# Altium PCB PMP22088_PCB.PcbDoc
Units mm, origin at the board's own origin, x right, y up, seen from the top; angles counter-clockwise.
Board outline 25.4 x 38.1 mm, 2 copper layers (Top Layer, Bottom Layer), stack 1.575 mm thick; 47 components, 29 nets, 105 pads, 52 vias.
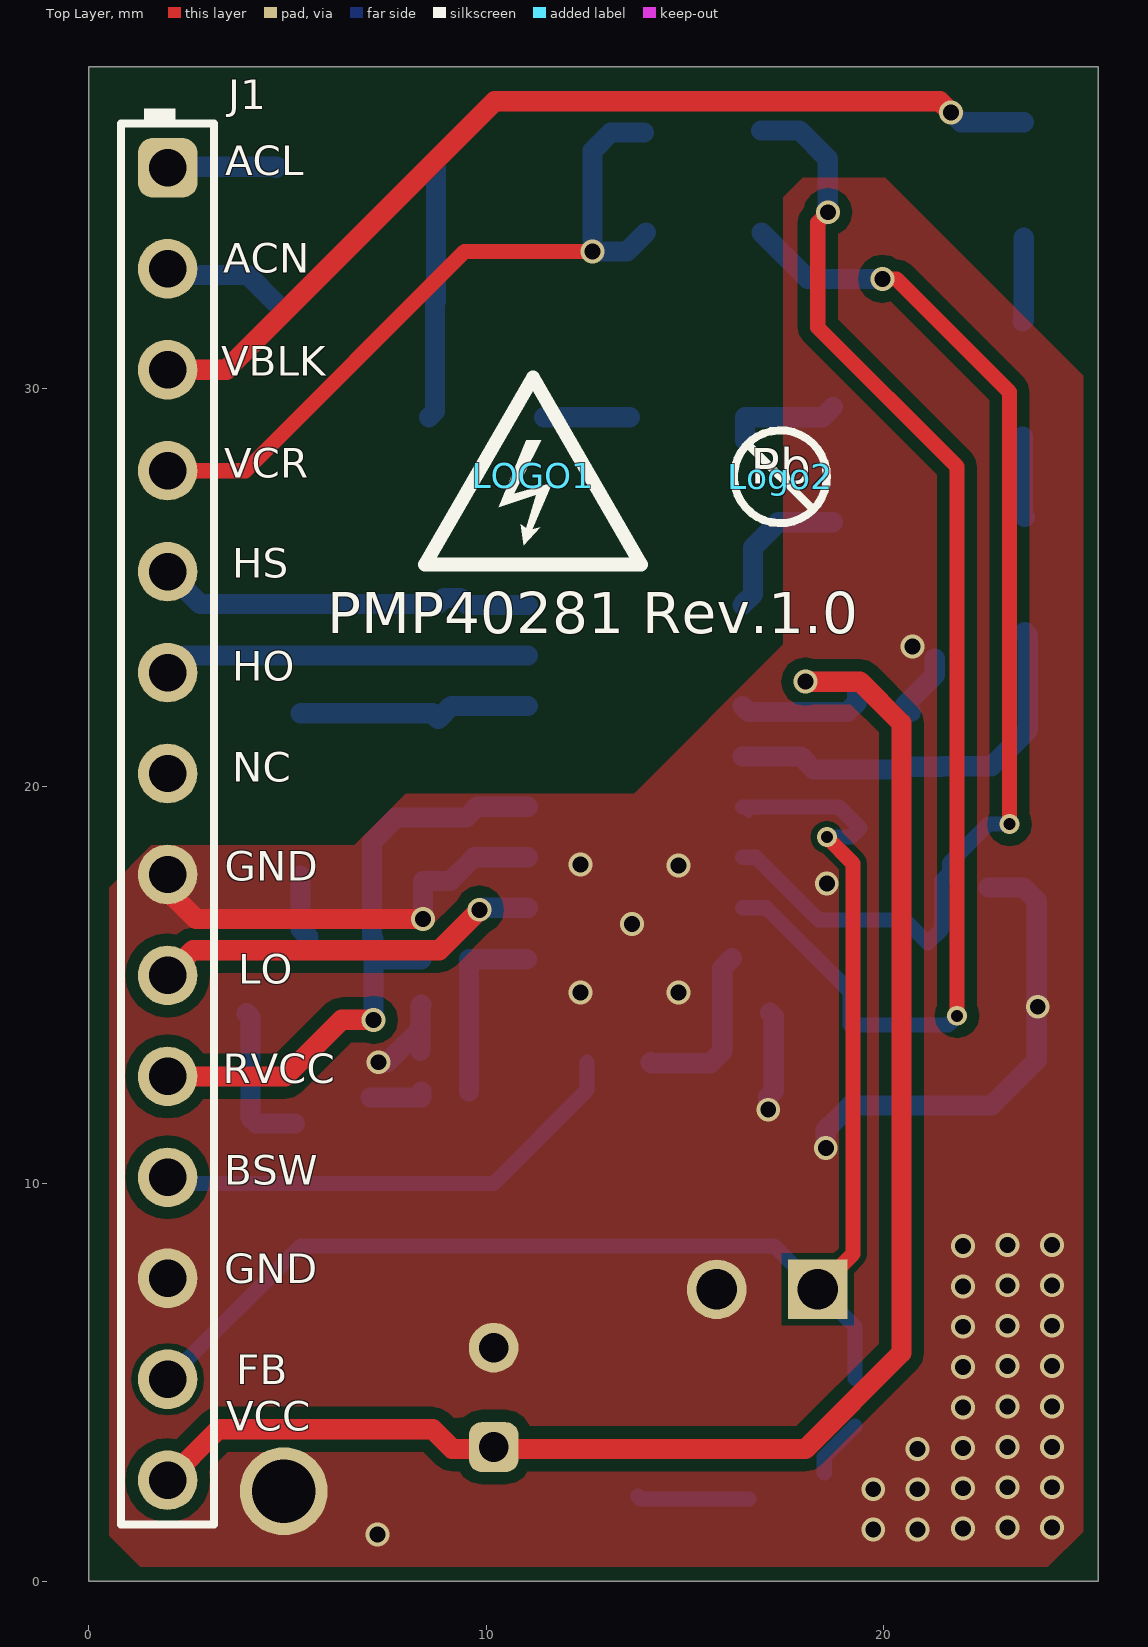
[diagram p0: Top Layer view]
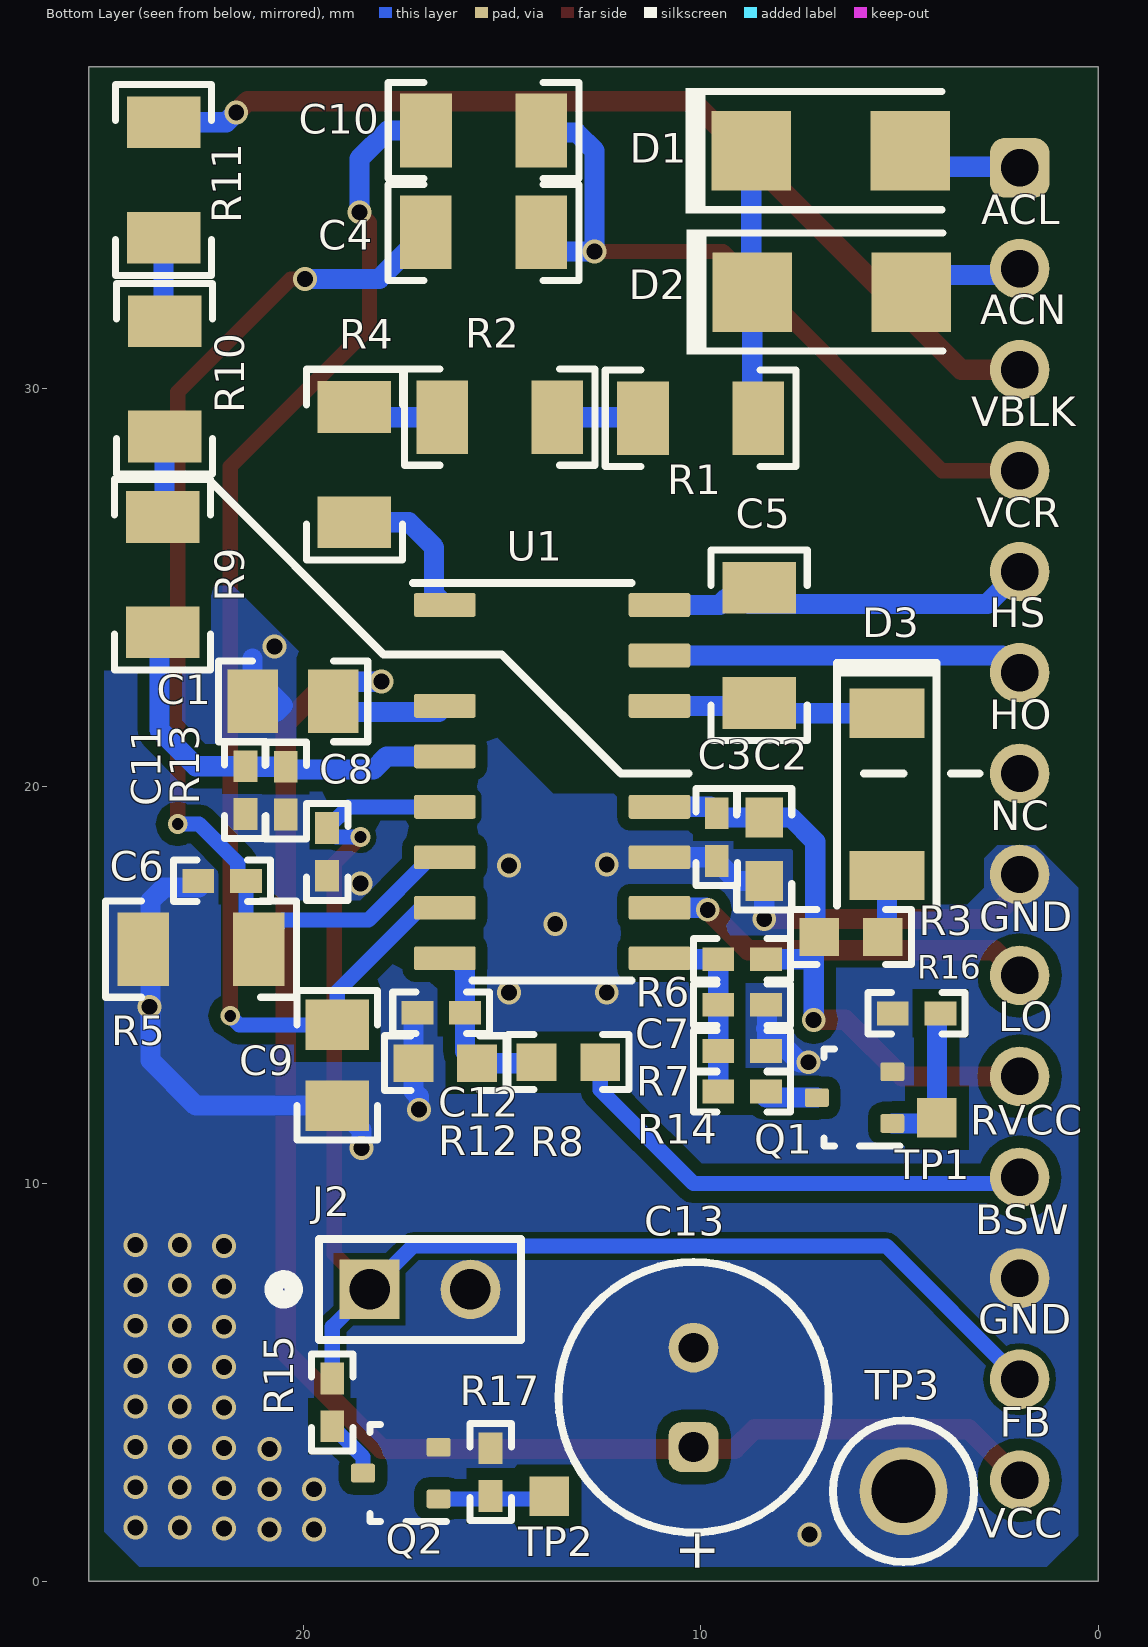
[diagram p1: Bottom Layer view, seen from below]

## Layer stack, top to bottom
Top Solder: solder mask 0.0102, Solder Resist, Dk 3.5
Top Layer: signal copper 0.0356
Dielectric1: core 1.5037, FR-4, Dk 4.8
Bottom Layer: signal copper 0.0356
Bottom Solder: solder mask 0.0102, Solder Resist, Dk 3.5

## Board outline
0,0 25.4,0 25.4,38.1 0,38.1

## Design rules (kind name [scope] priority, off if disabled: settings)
AcuteAngle [All] p1: minimum=4.50000000000000E+0001 checktracksonly=FALSE
AssemblyTestPointUsage [All] p1: valid=2
BoardOutlineClearance BoardOutlineClearance_MountingHoles [OnCopper and InComponentClass('Mounting Holes')] p1: gap=0.3
BoardOutlineClearance BoardOutlineClearance_Poly [OnCopper and IsPoly] p2: gap=0.3
BoardOutlineClearance [OnCopper and Not InComponentClass('Logo') and not InComponentClass('FiducialMark') and not InRegion(1000,500,4000,800) and not InPoly] p3: gap=0.3
Clearance Clearance_FB [InNet('FB') vs InNet('GND')] p1: gap=0.152
Clearance Clearance_Keepouts [((IsTrack Or IsArc) And Not InPoly) And IsFree and IsKeepOut vs ((IsTrack Or IsArc) And Not InPoly) And IsFree and IsKeepOut] p2: gap=0.2
Clearance Clearance_Poly [InPolygon] p3: gap=0.3
Clearance [All] p4: gap=0.2
ComponentClearance ComponentClearance_TPPAD [InComponent('TP1') vs InComponent('J1')] p1: gap=0.254 collisioncheckmode=3 verticalgap=0.254 showdistances=FALSE
ComponentClearance ComponentClearance_MountingHoles_FiducialMarks [InComponentClass('Mounting Holes') vs InComponentClass('FiducialMark')] p2: gap=1.27 collisioncheckmode=3 verticalgap=0.254 showdistances=FALSE
ComponentClearance ComponentClearance_Shunt [InComponentClass('Header') vs InComponentClass('Shunt')] p3: gap=0 collisioncheckmode=3 verticalgap=0 showdistances=FALSE
ComponentClearance ComponentClearance_Logo [InComponentClass('Logo')] p4: gap=1.27 collisioncheckmode=3 verticalgap=0.254 showdistances=FALSE
ComponentClearance ComponentClearance_ScrewToNut [(HasFootprint('NY PMS 440 0025 PH')) vs (HasFootprint('Keystone_1902C'))] p5: gap=0.127 collisioncheckmode=3 verticalgap=0.254 showdistances=FALSE
ComponentClearance ComponentClearance_MountingHoles [InComponentClass('Mounting Holes')] p6: gap=6.35 collisioncheckmode=3 verticalgap=2540 showdistances=FALSE
ComponentClearance ComponentClearance_SmallPassives [HasFootprint('0201*') or HasFootprint('0402*') or HasFootprint('0508') or HasFootprint('0603*') or HasFootprint('0612') or HasFootprint('0805*') or HasFootprint('0815*') or HasFootprint('0830*') or HasFootprint('1206*') or HasFootprint('1210*') or HasFootprint('1808*') or HasFootprint('1812*') or HasFootprint('1825*') or HasFootprint('2010*') or HasFootprint('2220*') or HasFootprint('2225*') or HasFootprint('2512*') or HasFootprint('2728*') or HasFootprint('3518*') vs HasFootprint('0201*') or HasFootprint('0402*') or HasFootprint('0508') or HasFootprint('0603*') or HasFootprint('0612') or HasFootprint('0805*') or HasFootprint('0815*') or HasFootprint('0830*') or HasFootprint('1206*') or HasFootprint('1210*') or HasFootprint('1808*') or HasFootprint('1812*') or HasFootprint('1825*') or HasFootprint('2010*') or HasFootprint('2220*') or HasFootprint('2225*') or HasFootprint('2512*') or HasFootprint('2728*') or HasFootprint('3518*')] p7: gap=0.38 collisioncheckmode=3 verticalgap=0.254 showdistances=FALSE
ComponentClearance ComponentClearance_THtoSMT [IsThruComponent vs IsSMTComponent] p8: gap=1.016 collisioncheckmode=3 verticalgap=0.762 showdistances=FALSE
ComponentClearance ComponentClearance_THtoTH [IsThruComponent vs IsThruComponent] p9: gap=0.762 collisioncheckmode=3 verticalgap=0.762 showdistances=FALSE
ComponentClearance [All] p10: gap=0.762 collisioncheckmode=3 verticalgap=0.254 showdistances=FALSE
DiffPairsRouting [All] p1: maxlimit=2.54 minlimit=0.254 mostfreqgap=0.254 toplayer_minwidth=0.381 toplayer_maxwidth=0.381 toplayer_prefwidth=0.381 bottomlayer_minwidth=0.381 bottomlayer_maxwidth=0.381 bottomlayer_prefwidth=0.381 maxuncoupledlength=25.4
FabricationTestPointUsage TestPointUsage [All] p1: valid=2 allowmultiple=FALSE
FabricationTestpoint Testpoint [All] p1: side=3 testpointundercomponent=TRUE minsize=1.016 maxsize=2.54 preferedsize=1.524 minholesize=0 maxholesize=1.016 preferedholesize=0.813 testpointgrid=0.025 allowsidetop=TRUE allowsidebottom=TRUE usegrid=TRUE gridtolerance=0
FanoutControl Fanout_LCC [IsLCC] p1: bgadir=Out bgaviamode=Centered fanoutstyle=Auto fanoutdirection=Alternating viagrid=0.025 // Fanout_LCC (Default Rule)
FanoutControl Fanout_BGA [IsBGA] p2: bgadir=Out bgaviamode=Centered fanoutstyle=Auto fanoutdirection=Alternating viagrid=0.025 // Fanout_BGA (Default Rule)
FanoutControl Fanout_Default [All] p4: bgadir=Out bgaviamode=Centered fanoutstyle=Auto fanoutdirection=Alternating viagrid=0.025 // Fanout_Default (Default Rule)
FanoutControl Fanout_Small [(CompPinCount < 5)] p5: bgadir=Out bgaviamode=Centered fanoutstyle=Auto fanoutdirection=OutThenIn viagrid=0.025 // Fanout_Small (Default Rule)
HoleSize [All] p1: absolutevalues=TRUE maxlimit=6.375 minlimit=0.2 maxpercent=80.000 minpercent=20.000
HoleToHoleClearance [All] p1: gap=0.2 allowstackedmicrovias=TRUE
MinimumAnnularRing MinimumAnnularRing_ThermalPadVias [IsVia and InAnyComponent] p1: minimumring=0.1
MinimumAnnularRing [All] p2: minimumring=0.1
MinimumSolderMaskSliver MinimumSolderMaskSliver_Logo [InComponentClass('Logo') vs InComponentClass('Logo')] p1: minsoldermaskwidth=0
MinimumSolderMaskSliver [All] p2: minsoldermaskwidth=0
PlaneConnect [All] p1: planeconnectstyle=Direct reliefexpansion=0.254 reliefentries=4 reliefconductorwidth=0.254 reliefairgap=0.254
PolygonConnect [All] p1: connectstyle=Direct reliefconductorwidth=0.254 reliefentries=4 polygonreliefangle="90 Angle" airgapwidth=0.254
RoutingVias ThermalPadVias [IsVia and InAnyComponent] p1: holewidth=0.2 width=0.5 viastyle="Through Hole" minholewidth=0.2 minwidth=0.2 maxholewidth=0.33 maxwidth=0.6
RoutingVias [All] p2: holewidth=0.406 width=0.864 viastyle="Through Hole" minholewidth=0.2 minwidth=0.4 maxholewidth=1.016 maxwidth=1.651
SilkToBoardRegionClearance [Not ((IsComment or IsDesignator) And (Hide <> 'False')) and not InRegion(1000,500,4000,800)] p1:
SilkToSilkClearance SilkToSilkClearance_Pb-FreeLogo [(HasFootprint('Pb-Free_Overlay_Medium') OR HasFootprint('Pb-Free_Overlay_Small')) vs (HasFootprint('Pb-Free_Overlay_Medium') OR HasFootprint('Pb-Free_Overlay_Small'))] p1: silktosilkclearance=0
SilkToSilkClearance [All] p2: silktosilkclearance=0
SilkToSolderMaskClearance SilkToComponentPadClearance [(IsPad or IsFill or IsRegion) and InAnycomponent] p1: minsilkscreentomaskgap=0 clearancetoexposedcopper=TRUE
SilkToSolderMaskClearance "Silk to Solder Mask Opening" [All] p2: minsilkscreentomaskgap=0 clearancetoexposedcopper=FALSE
SolderMaskExpansion [All] p1: expansion=0.05
Width [All] p1: maxlimit=2.54 minlimit=0.381 preferedwidth=0.381 checkconnectedcopper=TRUE
14 further rules are at their usual default settings.

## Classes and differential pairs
component class Header: J1 J2
component class AssemblyNote: ZZ1 ZZ2 ZZ3 ZZ4

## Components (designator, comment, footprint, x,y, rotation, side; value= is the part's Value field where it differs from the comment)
C1 "C2012X7R1V225K085AC" 0805_HV 20.263,22.136 r180 bottom
C2 "GRM188Z71C475KE21D" 0603#1 6.298,13.233 r90 bottom
C3 "GRM155R71C104KA88D" 0402 9.601,18.72 r90 bottom
C4 "GRM31A5C2J151JW01D" 1206 15.471,33.934 r0 bottom
C5 "C1206C225K4RACTU" 1206 8.534,23.546 r90 bottom
C6 "GRM1555C1H3R3CA01D" 0402 22.049,17.619 r0 bottom
C7 "GRM155R71C154KA12D" 0402 8.966,14.503 r180 bottom
C8 "GRM1555C1H470FA01D" 0402 19.406,18.348 r270 bottom
C9 "GRM2195C1H153JA01D" 0805_HV 19.152,12.979 r90 bottom
C10 "GRM31A5C2J151JW01D" 1206 15.469,36.5 r0 bottom
C11 "GRM1555C1H221JA01D" 0402 21.463,19.901 r270 bottom
C12 "GRM1555C1H3R9CA01D" 0402 16.535,14.3 r0 bottom
C13 "35ZLQ120MEFC6.3X11" ZLQ_630x1100 10.185,4.623 r90 bottom
D1 "MURA160T3G" SMA 6.732,35.992 r180 bottom
D2 "MURA160T3G" SMA 6.707,32.436 r180 bottom
D3 "ES1JAF" SMAF 5.321,19.796 r270 bottom
J1 "4-644694-4" TE_4-644694-4 -0.051,19.05 r270 top locked
J2 "5-146261-1" CONN_5-146261-1 17.069,7.341 r180 bottom
LOGO1 "DANGER HIGH VOLTAGE" IEC_HighVoltage_Small 11.176,27.813 r0 top
Logo2 "Pb-Free Symbol" Pb-Free_Overlay_Small 17.399,27.788 r0 top
Q1 "2N7002KW" SOT-323 6.133,12.164 r0 bottom
Q2 "2N7002KW" SOT-323 17.551,2.718 r0 bottom
R1 "CRCW12061K65FKEA" 1206 10.008,29.261 r0 bottom
R2 "CRCW12061K65FKEA" 1206 15.062,29.286 r0 bottom
R3 "CRCW06032R20JNEA" 0603#2 6.223,16.205 r0 bottom
R4 "CRCW12061K65FKEA" 1206 18.72,28.092 r90 bottom
R5 "CRCW1206174RFKEA" 1206 22.578,15.9 r180 bottom
R6 "CRCW0402750KFKED" 0402 8.966,15.646 r180 bottom
R7 "CRCW0402487KFKED" 0402 8.966,13.335 r0 bottom
R8 "CRCW060335K7FKEA" 0603#2 13.335,13.056 r180 bottom
R9 "CRCW12064M99FKEA" 1206 23.546,25.324 r90 bottom
R10 "CRCW12064M99FKEA" 1206 23.495,30.251 r90 bottom
R11 "CRCW12064M99FKEA" 1206 23.52,35.255 r90 bottom
R12 "CRCW060310K0FKEA" 0603#2 16.434,13.03 r180 bottom
R13 "CRCW0402140KFKED" 0402 20.447,19.888 r90 bottom
R14 "CRCW0402487KFKED" 0402 8.966,12.319 r0 bottom
R15 "CRCW0402487KFKED" 0402 19.279,4.496 r90 bottom
R16 "CRCW040210K0FKED" 0402 4.574,14.286 r180 bottom
R17 "CRCW040210K0FKED" 0402 15.291,2.743 r270 bottom
TP1 "TESTPOINT" PAD_1MM_SQUARE 4.064,11.659 r0 top
TP2 "TESTPOINT" PAD_1MM_SQUARE 13.818,2.134 r90 top
TP3 "5011" Keystone5011 4.902,2.261 r90 bottom
U1 "UCC25630-1DDBR" DDB0014A 13.743,20.117 r180 bottom
ZZ1 "This Assembly Note is for PCB labels only" AssemblyNoteLabel 4.699,100.025 r0 top
ZZ2 "These assemblies are ESD sensitive, ESD precautions shall be observed." AssemblyNote 4.699,97.259 r0 top
ZZ3 "These assemblies must be clean and free from flux and all contaminants. Use of no clean flux is not acceptable." AssemblyNote 4.699,95.01 r0 top
ZZ4 "These assemblies must comply with workmanship standards IPC-A-610 Class 2, unless otherwise specified." AssemblyNote 4.699,92.761 r0 top

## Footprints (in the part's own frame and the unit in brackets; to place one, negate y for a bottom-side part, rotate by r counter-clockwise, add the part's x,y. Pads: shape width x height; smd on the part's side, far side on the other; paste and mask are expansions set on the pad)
0402 [mm] "0402 from SM-752 data"
  rect 0.8x0.6 smd: 1(-0.6,0) 2(0.6,0)
  silkscreen extent -1.22,-0.52 1.22,0.52, body extent -0.55,-0.3 0.55,0.3, height 0.6
0603#1 [mm] "0603 from SM-752 data"
  rect 1x0.95 smd: 1(4.382,2.108) 2(5.982,2.108)
  silkscreen extent 3.66,1.42 6.71,2.8, body extent 4.31,1.63 6.06,2.58, height 1
0603#2 [mm] "0603 from SM-752 data"
  rect 1x0.95 smd: 1(-0.8,0) 2(0.8,0)
  silkscreen extent -1.52,-0.69 1.52,0.69, body extent -0.87,-0.47 0.87,0.47, height 1
0805_HV [mil] "0805 with 30mil clearance between pads"
  rect 50x63 smd: 1(-40,0) 2(40,0)
  silkscreen extent -74,-40 74,40, body extent -43,-29 43,29, height 57
1206 [mm] "1206 from SM-752 data"
  rect 1.3x1.85 smd: 1(-1.45,0) 2(1.45,0)
  silkscreen extent -2.4,-1.21 2.4,1.21, body extent -1.7,-0.9 1.7,0.9, height 1.35
AssemblyNote [mm] "Assembly Note"
AssemblyNoteLabel [mm] "Assembly Note for PCB Labels"
CONN_5-146261-1 [mm] "Sullins"
  rect 1.5x1.5 hole 1.02: 1(-1.27,0)
  round 1.5 hole 1.02: 2(1.27,0)
  silkscreen extent -3.68,-1.27 2.54,1.27, body extent -2.51,-1.27 2.51,1.27, height 10.87
DDB0014A [mm] "SMD, 14-Leads, Body 3.9x9.9mm, Pitch 1.27mm"
  rrect17% 1.55x0.6 smd: 1(-2.7,4.445) 3(-2.7,1.905) 4(-2.7,0.635) 5(-2.7,-0.635) 6(-2.7,-1.905) 7(-2.7,-3.175) 8(-2.7,-4.445) 9(2.7,-4.445) 10(2.7,-3.175) 11(2.7,-1.905) 12(2.7,-0.635) 14(2.7,1.905) 15(2.7,3.175) 16(2.7,4.445)
  silkscreen extent -3.5,-5 2,5, body extent -3.01,-4.95 3.01,4.95, height 1.75
IEC_HighVoltage_Small [mm]
  silkscreen extent -2.72,-2.24 2.72,2.47
Keystone5011 [mil] "Keystone Multipurpose loops"
  round 87 hole 63: 1(0,0)
  silkscreen extent -70,-70 70,70, body extent -63,-63 63,62, height 319
PAD_1MM_SQUARE [mm]
  rect 1x1 smd far side: 1(0,0)
Pb-Free_Overlay_Small [mm]
  silkscreen extent -1.16,-1.17 1.17,1.17
SMA [mm] "Molded Diode, 2-Leads, Body 4.3x2.6mm, IPC Medium Density, based on OnSemi component dimensions and land pattern"
  rect 2x2 smd: 1(-2,0) 2(2,0)
  silkscreen extent -3.66,-1.57 2.79,1.57, body extent -2.6,-1.3 2.6,1.3, height 2.42
SMAF [mm] "SMD, 2-Leads, Body 3.8x2.5mm"
  rect 1.24x1.89 smd: 1(-2.04,0) 2(2.04,0)
  silkscreen extent -3.4,-1.3 2.8,1.3, body extent -2.35,-1.25 2.35,1.25, height 1
SOT-323 [mm] "Diodes Inc recommended land pattern.  2016-02-24"
  rrect21% 0.6x0.47 smd: 1(-0.95,0.65) 2(-0.95,-0.65) 3(0.95,0)
  silkscreen extent -1.14,-1.22 0.77,1.22, body extent -1.13,-1.13 1.12,1.12, height 1.13
TE_4-644694-4 [mm] "Header, 100 mil, 14x1, R/A, TH"
  rrect50% 1.5x1.5 hole 0.94: 1(-16.51,2.032)
  round 1.5 hole 0.94: 2(-13.97,2.032) 3(-11.43,2.032) 4(-8.89,2.032) 5(-6.35,2.032) 6(-3.81,2.032) 7(-1.27,2.032) 8(1.27,2.032) 9(3.81,2.032) 10(6.35,2.032) 11(8.89,2.032) 12(11.43,2.032) 13(13.97,2.032) 14(16.51,2.032)
  silkscreen extent -18,0.86 17.63,3.2, body extent -17.63,-5.74 17.63,3.2, height 6.67
ZLQ_630x1100 [mm] "TH, 2-Leads, Dia 6.3mm, Pin Spacing 2.5mm"
  rrect50% 1.25x1.25 hole 0.75: 1(-1.25,0)
  round 1.25 hole 0.75: 2(1.25,0)
  silkscreen extent -3.4,-3.4 3.41,3.4, body extent -3.4,-3.4 3.41,3.4, height 12.51

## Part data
C1: "CAP, CERM, 2.2 μF, 35 V, +/- 10%, X7R, 0805"
C2: "CAP, CERM, 4.7 μF, 16 V, +/- 10%, X7R, 0603"
C3: "CAP, CERM, 0.1 μF, 16 V, +/- 10%, X7R, 0402"
C4 C10: "CAP, CERM, 150 pF, 630 V, +/- 5%, C0G/NP0, 1206"
C5: "CAP, CERM, 2.2 μF, 16 V, +/- 10%, X7R, 1206"
C6: "CAP, CERM, 3.3 pF, 50 V, +/- 5%, C0G/NP0, 0402"
C7: "CAP, CERM, 0.15 μF, 16 V, +/- 10%, X7R, 0402"
C8: "CAP, CERM, 47 pF, 50 V, +/- 1%, C0G/NP0, 0402"
C9: "CAP, CERM, 0.015 μF, 50 V, +/- 5%, C0G/NP0, 0805"
C11: "CAP, CERM, 220 pF, 50 V, +/- 5%, C0G/NP0, 0402"
C12: "CAP, CERM, 3.9 pF, 50 V, +/- 5%, C0G/NP0, 0402"
C13: "CAP, AL, 120 μF, 35 V, +/- 20%, TH"
D1 D2: "Diode, Ultrafast, 600 V, 1 A, AEC-Q101, SMA"
D3: "Diode, Ultrafast, 600 V, 1 A, AEC-Q101, SMAF"
J1: "Header, 100 mil, 14x1, Tin, R/A, TH"
J2: "Header, 100mil, 2x1, Gold, TH"
LOGO1: library part IEC_HighVoltage, "IEC 61010-1 High Voltage Warning"
Logo2: library part Pb-Free
Q1 Q2: "MOSFET, N-CH, 60 V, 0.31 A, SOT-323"
R1 R2 R4: "RES, 1.65 k, 1%, 0.25 W, 1206"
R3: "RES, 2.2, 5%, 0.1 W, 0603"
R5: "RES, 174, 1%, 0.25 W, 1206"
R6: "RES, 750 k, 1%, 0.063 W, 0402"
R7 R14 R15: "RES, 487 k, 1%, 0.063 W, 0402"
R8: "RES, 35.7 k, 1%, 0.1 W, 0603"
R9 R10 R11: "RES, 4.99 M, 1%, 0.25 W, 1206"
R12: "RES, 10.0 k, 1%, 0.1 W, 0603"
R13: "RES, 140 k, 1%, 0.063 W, 0402"
R16 R17: "RES, 10.0 k, 1%, 0.063 W, 0402"
TP1 TP2: library part PAD_1MM_SQUARE, "1.0x1.0mm pad, square, SMD"
TP3: "Test Point, Multipurpose, Black, TH"
U1: "Enhanced LLC Resonant Controller with Driver, DDB0014A (SOIC-14)"
ZZ1: library part AssemblyNoteLabel
ZZ2 ZZ3 ZZ4: library part AssemblyNote

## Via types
v1: diameter 0.6, hole 0.4, Top Layer to Bottom Layer, 49 vias
v2: diameter 0.5, hole 0.3, Top Layer to Bottom Layer, 3 vias

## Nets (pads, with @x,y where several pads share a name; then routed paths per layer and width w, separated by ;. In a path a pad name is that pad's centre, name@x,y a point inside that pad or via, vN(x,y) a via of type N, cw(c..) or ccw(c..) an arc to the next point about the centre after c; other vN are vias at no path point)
ACL: D1.2 J1.1 | length 2.8
  Bottom Layer w0.508: J1.1 2.007,35.585 4.732,35.585 D1.2@4.707,35.56
ACN: D2.2 J1.2 | length 3.1
  Bottom Layer w0.508: J1.2 2.134,32.868 3.996,32.868 D2.2@4.707,32.156
BLK: C11.1 R9.1 R13.2 U1.4 | length 10.2
  Bottom Layer w0.508: U1.4 17.907,20.752 18.237,20.422 20.38,20.422 R13.2 21.45,20.488 C11.1 22.711,20.501 23.622,21.412 23.622,23.798 R9.1
BSW: J1.11 R8.2 | length 12.3
  Bottom Layer w0.381: J1.11 2.134,10.008 10.185,10.008 12.535,12.357 R8.2
FB: C8.1 J1.13 J2.1 R15.2 U1.5 | length 37.5
  Top Layer w0.254: J2.1@18.324,7.036 18.288,7.072 J2.1@18.448,7.232
  Top Layer w0.381: J2.1 19.228,8.23 19.228,18.059 v2(18.567,18.72)
  Bottom Layer w0.254: U1.5 U1.5@16.595,19.329
  Bottom Layer w0.381: J1.13 5.335,8.434 17.246,8.434 J2.1 19.279,6.401 R15.2 ; U1.5 18.872,19.482 C8.1 19.177,18.72 v2(18.567,18.72)
GND: C1.1 C2.1 C3.1 C6.2 C7.2 C8.2 C9.1 C11.2 C12.2 C13.2 J1.8 J1.12 J2.2 Q1.2 Q2.2 R5.1 R7.1 R12.1 R13.1 R16.1 R17.1 TP3.1 U1.11 | length 29.7
  Top Layer w0.508: J1.8 1.981,17.374 2.692,16.662 v1(8.407,16.662)
  Bottom Layer w0.508: v1(7.29,13.056) 7.509,13.056 7.585,13.132 8.357,13.903 8.341,13.919 ; 8.315,13.945 8.341,13.919 ; R7.1@8.341,13.335 8.341,13.919 ; C7.2 8.341,14.478 8.341,13.919 ; v1(8.407,16.662) 8.406,16.664 C2.1 9.096,17.615 C3.1 9.693,18.212 U1.11 ; v1(17.094,11.862) 17.094,12.192 17.234,12.332 R12.1 17.234,14.202 C12.2 ; v1(18.542,10.897) 18.542,11.354 18.644,11.455 18.749,11.561 C9.1 22.708,11.963 23.851,13.106 23.851,15.9 23.851,17.12 23.52,17.45 C6.2@22.635,17.45 ; C1.1@20.688,21.869 20.523,22.034 21.285,22.796 21.285,23.216
  other v1: 7.264,1.168 19.736,1.295 20.853,1.295 21.996,1.321 23.114,1.346 24.232,1.346 19.736,2.311 20.853,2.311 21.996,2.337 23.114,2.362 24.232,2.362 20.853,3.327 21.996,3.353 23.114,3.378 24.232,3.378 21.996,4.369 23.114,4.394 24.232,4.394 21.996,5.385 23.114,5.41 24.232,5.41 21.996,6.401 23.114,6.426 24.232,6.426 21.996,7.417 23.114,7.442 24.232,7.442 21.996,8.433 23.114,8.458 24.232,8.458 23.876,14.453 12.37,14.808 14.834,14.808 13.665,16.535 18.567,17.551 14.834,18.009 12.37,18.034 20.726,23.52
HB: C5.1 D3.1 U1.14 | length 5.9
  Bottom Layer w0.508: D3.1 8.642,21.836 8.788,21.689 9.121,22.022 U1.14
HO: J1.6 U1.15 | length 9.2
  Bottom Layer w0.508: J1.6 2.413,23.292 U1.15
HS: C5.2 J1.5 U1.16 | length 9.5
  Bottom Layer w0.508: J1.5 2.792,24.589 8.788,24.589 8.939,24.74 9.347,24.74 9.525,24.562 U1.16
LL: C7.1 R6.1 R7.2 R14.2 U1.9 | length 4.8
  Bottom Layer w0.254: U1.9@11.017,15.646 U1.9
  Bottom Layer w0.508: R14.2 C7.1 R6.1 U1.9@11.017,15.646
LO: J1.9 U1.10 | length 9.8
  Top Layer w0.508: J1.9 2.616,15.875 8.814,15.875 v1(9.83,16.891)
  Bottom Layer w0.508: v1(9.83,16.891) 9.881,16.942 U1.10
NetC4_2: C4.2 C6.1 R5.2 U1.6 | length 28.5
  Top Layer w0.381: v1(19.964,32.766) 20.32,32.766 23.165,29.921 v2(23.165,19.05)
  Bottom Layer w0.381: U1.6 16.789,18.212 18.364,16.637 20.523,16.637 21.105,16.055 21.449,16.399 C6.1 21.653,17.824 21.653,18.072 22.631,19.05 v2(23.165,19.05)
  Bottom Layer w0.508: C4.2 18.089,32.766 v1(19.964,32.766)
NetC9_2: C9.2 C10.2 U1.7 | length 32.3
  Top Layer w0.381: v1(18.593,34.442) 18.339,34.188 18.339,31.547 21.844,28.042 v2(21.844,14.224)
  Bottom Layer w0.381: U1.7 17.043,16.942 19.152,14.834 C9.2 21.615,13.995 v2(21.844,14.224)
  Bottom Layer w0.508: C10.2 17.882,36.5 18.593,35.789 v1(18.593,34.442)
NetC12_1: C12.1 R8.1 R12.2 U1.8 | length 4.4
  Bottom Layer w0.508: R8.1 14.16,13.03 R12.2 15.935,13.332 C12.1 15.935,15.427 U1.8@16.18,15.672
NetD1_1: D1.1 D2.1 R1.1 | length 6.4
  Bottom Layer w0.508: R1.1@8.558,29.286 8.707,29.435 8.707,32.156 8.732,32.182 D1.1@8.732,35.585
NetD3_2: D3.2 R3.1 | length 1.6
  Bottom Layer w0.508: D3.2 5.321,16.409 R3.1@5.525,16.205
NetQ1_1: Q1.1 R16.2 TP1.1 | length 3.8
  Bottom Layer w0.508: R16.2 4.064,14.195 TP1.1 4.208,11.514 Q1.1
NetQ1_3: Q1.3 R14.1 | length 1.4
  Bottom Layer w0.508: Q1.3 8.366,12.164 R14.1
NetQ2_1: Q2.1 R17.2 TP2.1 | length 2.8
  Bottom Layer w0.381: TP2.1 13.883,2.068 Q2.1
NetQ2_3: Q2.3 R15.1 | length 1.5
  Bottom Layer w0.381: Q2.3 18.501,3.119 R15.1
NetR1_2: R1.2 R2.1 | length 2.2
  Bottom Layer w0.508: R1.2@11.458,29.286 R2.1
NetR2_2: R2.2 R4.2 | length 2.9
  Bottom Layer w0.508: R2.2@16.512,28.704 R2.2 18.464,29.286 R4.2
NetR4_1: R4.1 U1.1 | length 3.8
  Bottom Layer w0.508: U1.1 16.713,24.832 16.713,26.01 17.346,26.642 R4.1
NetR9_2: R9.2 R10.1 | length 2
  Bottom Layer w0.508: R10.1 23.495,26.825 R9.2
NetR10_2: R10.2 R11.1 | length 2.1
  Bottom Layer w0.508: R10.2 23.52,31.727 R11.1
RVCC: C2.2 C3.2 J1.10 R3.2 R6.2 U1.12 | length 16.1
  Top Layer w0.508: J1.10 4.942,12.7 6.364,14.122 v1(7.163,14.122)
  Bottom Layer w0.508: v1(7.163,14.122) R3.2@7.163,16.167 ; R6.2 7.391,15.646 7.163,15.875 R3.2@7.163,16.167 ; U1.12 9.763,19.482 C3.2 9.496,19.215 C2.2 7.734,19.215 7.125,18.605 7.125,16.205 R3.2@7.163,16.167
VBLK: J1.3 R11.2 | length 24.6
  Top Layer w0.508: J1.3 3.454,30.48 10.211,37.236 21.412,37.236 v1(21.692,36.957)
  Bottom Layer w0.508: v1(21.692,36.957) 21.943,36.705 R11.2
VCC: C1.2 C13.1 J1.14 U1.3 | length 43.7
  Top Layer w0.508: J1.14 3.261,3.819 8.652,3.819 9.144,3.327 18.034,3.327 20.447,5.74 20.447,21.59 19.406,22.631 v1(18.034,22.631)
  Bottom Layer w0.508: U1.3 16.595,21.869 19.088,21.869 19.329,22.111 19.329,22.53 19.228,22.631 v1(18.034,22.631)
VCR: C4.1 C10.1 J1.4 | length 18.6
  Top Layer w0.381: J1.4 3.937,27.94 9.449,33.452 v1(12.675,33.452)
  Bottom Layer w0.254: C10.1@13.968,36.449 C10.1
  Bottom Layer w0.508: C10.1@13.968,36.449 13.132,36.449 12.675,35.992 v1(12.675,33.452) 13.538,33.452 C4.1
pads on no net: J1.7

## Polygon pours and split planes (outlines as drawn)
GND on Top Layer "TOP_LAYER_GND_P000" (solid, remove dead copper, pour order 0): 6.68,18.517 7.976,19.812 13.716,19.812 17.475,23.571 17.475,34.823 17.958,35.306 20.041,35.306 25.019,30.328 25.019,1.499 25.019,1.245 24.13,0.356 1.295,0.356 0.508,1.143 0.508,17.45 1.575,18.517
GND on Bottom Layer "BOTTOM_LAYER_GND_P002" (solid, remove dead copper, pour order 2): 5.182,17.018 6.579,17.018 6.833,17.272 6.833,18.669 7.976,19.812 13.716,19.812 16.205,22.301 19.025,22.301 21.768,25.044 24.206,25.044 25.019,24.232 25.019,1.499 25.019,1.245 24.13,0.356 1.295,0.356 0.508,1.143 0.508,16.459 0.508,17.45 1.575,18.517 2.54,18.517 2.87,18.186 2.87,17.45 3.302,17.018

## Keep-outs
Keep-Out Layer:
  text ".Layer_Name" at 14.656,-21.806 h1.52

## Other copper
Top Layer:
  text ".Layer_Name" at 14.656,-21.806 h1.52
Bottom Layer:
  text ".Layer_Name" at 14.656,-21.806 h1.52

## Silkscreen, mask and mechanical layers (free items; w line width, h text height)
Top Overlay:
  text "ACL" at 3.429,35.128 h1.27
  text "ACN" at 3.378,32.664 h1.27
  text "VBLK" at 3.327,30.074 h1.27
  text "VCR" at 3.404,27.508 h1.27
  text "HS" at 3.607,24.994 h1.27
  text "PMP40281 Rev.1.0" at 5.994,23.515 h1.78
  text "HO" at 3.607,22.403 h1.27
  text "NC" at 3.607,19.863 h1.27
  text "GND" at 3.424,17.374 h1.27
  text "LO" at 3.759,14.775 h1.27
  text "RVCC" at 3.373,12.275 h1.27
  text "BSW" at 3.404,9.72 h1.27
  text "GND" at 3.404,7.239 h1.27
  text "FB" at 3.703,4.706 h1.27
  text "VCC" at 3.454,3.531 h1.27
  text ".Layer_Name" at 14.656,-21.806 h1.52
Bottom Overlay:
  lines w0.203: 2.997,20.32 3.708,20.32 ; 4.902,20.32 5.893,20.32 ; 10.312,20.32 12.014,20.32 15.011,23.317 17.196,23.317 17.983,23.317 22.479,27.813
  text "ACL" at 2.946,33.884 h1.27
  text "ACN" at 2.972,31.369 h1.27
  text "VBLK" at 3.2,28.804 h1.27
  text "VCR" at 3.073,26.264 h1.27
  text "HS" at 2.743,23.749 h1.27
  text "HO" at 2.743,21.184 h1.27
  text "NC" at 2.718,18.644 h1.27
  text "GND" at 2.992,16.104 h1.27
  text "LO" at 2.515,13.581 h1.27
  text "RVCC" at 3.221,10.98 h1.27
  text "BSW" at 3.099,8.476 h1.27
  text "GND" at 3.023,5.969 h1.27
  text "FB" at 2.484,3.385 h1.27
  text "VCC" at 3.023,0.838 h1.27
  text ".Layer_Name" at 14.656,-21.806 h1.52
Top Paste:
  text ".Layer_Name" at 14.656,-21.806 h1.52
Bottom Paste:
  text ".Layer_Name" at 14.656,-21.806 h1.52
Top Solder:
  rectangle: 10.922,10.998 17.501,19.126
  region: 21.438,9.144 21.438,5.258 18.212,2.032 6.909,2.032 6.909,0.457 18.212,0.457 23.927,0.457 24.74,1.27 24.74,9.144
  text ".Layer_Name" at 14.656,-21.806 h1.52
  text ".Layer_Name" at 14.656,-21.806 h1.52
Bottom Solder:
  rectangle: 6.807,0.406 8.179,1.676
  region: 21.438,9.144 21.438,4.216 18.212,0.991 18.212,0.457 23.927,0.457 24.74,1.27 24.74,9.144
  text ".Layer_Name" at 14.656,-21.806 h1.52
Drill Guide:
  text ".Layer_Name" at 14.656,-21.806 h1.52
M1 Board Outline:
  the board outline again, w0.203
  text ".Layer_Name" at 14.656,-21.806 h1.52
M2 Board Dimensions:
  rectangle: 0,-6.985 3.175,-3.81
  rectangle: 3.175,-10.16 12.7,-6.985
  lines w0.178: 0,-6.985 25.4,-6.985 ; 3.175,-10.16 3.175,-3.81 ; 6.35,-10.16 6.35,-3.81 ; 12.7,-10.16 12.7,-3.81 ; 19.05,-10.16 19.05,-3.81 ; 0,-10.16 25.4,-10.16 25.4,-3.81 0,-3.81 0,-10.16
  text ".Layer_Name" at 14.656,-21.806 h1.52
M3 3D STEP Top:
  text ".Layer_Name" at 14.656,-21.806 h1.52
M4 3D STEP Bottom:
  text ".Layer_Name" at 14.656,-21.806 h1.52
M5 Assembly Top:
  lines w0.254: -7.417,-23.626 160.223,-23.626 ; -7.417,-18.462 160.274,-18.462 ; -7.417,-13.297 -7.417,-28.791 94.31,-28.791 160.274,-28.791 160.274,-13.297 -7.404,-13.297 -7.404,-28.791 32.614,-28.791 ; 55.194,-28.791 55.194,-13.297 ; 87.376,-18.462 87.376,-13.297 ; 108.712,-18.462 108.712,-13.297 ; 124.511,-28.956 124.511,-23.804
  text "COMPONENTS MARKED 'DNP' SHOULD NOT BE POPULATED." at 29.299,-8.09 h1.52
  text "ASSEMBLY VARIANT:" at 29.286,-11.024 h1.52
  text ".VariantName" at 55.601,-11.024 h1.52
  text "PCB VIEWED FROM TOP SIDE" at -5.804,-16.654 h1.52
  text "BOARD #:" at 57.099,-16.654 h1.52
  text ".PRJ_Number" at 70.955,-16.654 h1.52
  text "REV:" at 92.405,-16.654 h1.52
  text ".PCB_Rev" at 99.809,-16.654 h1.52
  text "SVN REV:" at 113.69,-16.654 h1.52
  text ".VersionControl_RevNumber" at 126.543,-16.654 h1.52
  text "TID #:" at 57.099,-21.819 h1.52
  text ".TID" at 70.955,-21.819 h1.52
  text "PLOT NAME =" at -5.804,-27.034 h1.52
  text ".plot_File_Name" at 14.656,-27.034 h1.52
  text "GENERATED    :" at 57.15,-27.034 h1.52
  text ".Print_Date" at 79.235,-27.034 h1.52
  text ".Print_Time" at 97.752,-27.034 h1.52
  text "TEXAS INSTRUMENTS" at 129.87,-27.034 h1.52
M6 Assembly Bottom:
  lines w0.254: -7.429,-18.474 160.261,-18.474 ; -7.379,-23.639 160.261,-23.639 ; 28.334,-28.969 28.334,-23.817 ; 44.133,-18.474 44.133,-13.31 ; 65.468,-18.474 65.468,-13.31 ; 97.65,-28.804 97.65,-13.31 ; 120.231,-28.804 160.249,-28.804 160.249,-13.31 -7.429,-13.31 -7.429,-28.804 58.534,-28.804 160.261,-28.804 160.261,-13.31
  text "COMPONENTS MARKED 'DNP' SHOULD NOT BE POPULATED." at 154.991,-8.077 h1.52
  text ".VariantName" at 128.473,-11.024 h1.52
  text "ASSEMBLY VARIANT:" at 154.864,-11.024 h1.52
  text ".VersionControl_RevNumber" at 26.302,-16.667 h1.52
  text "SVN REV:" at 39.154,-16.667 h1.52
  text ".PCB_Rev" at 53.035,-16.667 h1.52
  text "REV:" at 60.439,-16.667 h1.52
  text ".PRJ_Number" at 81.89,-16.667 h1.52
  text "BOARD #:" at 95.745,-16.667 h1.52
  text "PCB VIEWED FROM BOTTOM SIDE" at 158.648,-16.667 h1.52
  text ".TID" at 81.89,-21.831 h1.52
  text "TID #:" at 95.745,-21.831 h1.52
  text "TEXAS INSTRUMENTS" at 22.974,-27.047 h1.52
  text ".Print_Time" at 55.093,-27.047 h1.52
  text ".Print_Date" at 73.609,-27.047 h1.52
  text "GENERATED    :" at 95.694,-27.047 h1.52
  text ".plot_File_Name" at 138.189,-27.047 h1.52
  text "PLOT NAME =" at 158.648,-27.047 h1.52
M9 Title Sheet:
  drawing of 57 lines, arcs and shapes, not listed
  text "1" at 18.792,204.127 h1.78
  text "2" at 82.182,204.127 h1.78
  text "3" at 145.411,204.127 h1.78
  text "4" at 209.08,204.127 h1.78
  text "5" at 272.555,204.127 h1.78
  text "6" at 336.182,204.127 h1.78
  text "A" at -10.579,175.095 h1.78
  text "A" at 365.341,175.095 h1.78
  text "B" at -10.579,114.643 h1.78
  text "B" at 365.341,114.643 h1.78
  text "C" at -10.579,54.318 h1.78
  text "C" at 365.341,54.318 h1.78
  text "PROJECT TITLE:" at 288.125,7.048 h1.14
  text ".PRJ_Title" at 289.395,3.662 h1.78
  text "DESIGNED FOR:" at 288.125,-0.597 h1.14
  text ".PRJ_Customer" at 289.395,-4.153 h1.78
  text "D" at -10.579,-5.88 h1.78
  text "D" at 365.341,-5.88 h1.78
  text "FILE NAME:" at 288.125,-8.217 h1.14
  text ".PCB_File_Name_No_Path" at 289.395,-11.265 h1.78
  text "Texas Instruments (TI) and/or its licensors do not warrant the accuracy or completeness of this specification" at 161.9,-15.376 h1.14
  text "ENGINEER:" at 288.125,-15.583 h1.14
  text "LAYOUT BY:" at 326.352,-15.583 h1.14
  text "or any information contained therein. TI and/or its licensors do not warrant that this design will meet" at 160.757,-18.237 h1.14
  text ".PRJ_Engineer" at 289.395,-19.52 h1.78
  text ".PCB_Layout" at 327.635,-19.52 h1.78
  text "the specifications, will be suitable for your application or fit for any particular purpose, or will operate in" at 160.757,-21.099 h1.14
  text ".Layer_Name" at 14.656,-21.806 h1.52
  text "ALTIUM DESIGNER VERSION:" at 326.352,-23.457 h1.14
  text "an implementation. TI and/or its licensors do not warrant that the design is production worthy. You should" at 160.757,-23.961 h1.14
  text "completely validate and test your design implementation to confirm the system functionality for your application." at 161.9,-26.822 h1.14
  text ".print_Scale" at 289.395,-26.843 h1.78
  text ".Application_BuildNumber" at 327.635,-26.843 h1.78
  text "1" at 18.792,-32.093 h1.78
  text "2" at 82.182,-32.093 h1.78
  text "3" at 145.411,-32.093 h1.78
  text "4" at 209.08,-32.093 h1.78
  text "5" at 272.555,-32.093 h1.78
  text "6" at 336.182,-32.093 h1.78
M10 Fab Notes:
  drawing of 173 lines, arcs and shapes, not listed
  text "DESIGN INFORMATION" at 314.402,157.505 h1.52
  text "MIN. TRACK WIDTH:" at 298.03,152.933 h1.52
  text "8" at 325.874,152.933 h1.52
  text "MIL" at 329.805,152.933 h1.52
  text "MIN. CLEARANCE:" at 298.03,149.581 h1.52
  text "0.2" at 324.35,149.581 h1.52
  text "mm" at 329.805,149.581 h1.52
  text "MIN. VIA PAD SIZE:" at 298.03,146.228 h1.52
  text "24" at 325.113,146.228 h1.52
  text "MIL" at 329.805,146.228 h1.52
  text "0.05mm (2MIL)" at 315.683,142.628 h1.52
  text "MINIMUM ANNULAR RING" at 289.667,142.52 h1.52
  text "EXTERNAL" at 333.666,142.52 h1.52
  text "PER" at 294.747,139.522 h1.52
  text "IPC-D-275 CLASS 2 LEVEL C" at 300.335,139.522 h1.52
  text "MIL, HOLES" at 338.136,136.67 h1.52
  text "+/-" at 328.168,136.652 h1.52
  text "+/-" at 349.86,136.652 h1.52
  text "REGISTRATION TOLERANCES:" at 289.667,136.525 h1.52
  text "METAL" at 320.142,136.525 h1.52
  text "5" at 334.777,136.525 h1.52
  text "3" at 355.935,136.525 h1.52
  text "MIL" at 358.888,136.525 h1.52
  text "+/-" at 349.86,133.655 h1.52
  text "HOLE SIZE TOLERANCE (UNLESS OTHERWISE SPECIFIED):" at 289.667,133.528 h1.52
  text "3" at 355.935,133.528 h1.52
  text "MIL" at 358.888,133.528 h1.52
  text "MATERIAL:" at 287.768,128.208 h1.52
  text "FR-4 High Tg" at 312.824,124.643 h1.52
  text "FR-408" at 298.462,124.425 h1.52
  text "OTHER" at 336.257,124.425 h1.52
  text "X" at 308.889,124.333 h1.52
  text "62 MIL (1.6mm) +/-10%" at 306.592,120.292 h1.52
  text "THICKNESS:" at 289.667,120.184 h1.52
  text "X" at 303.337,120.184 h1.52
  text "OTHER" at 339.229,120.184 h1.52
  text "TOLERANCE:" at 289.667,116.17 h1.52
  text "X" at 310.986,116.17 h1.52
  text "ANSI IPC-6012 TYPE 3 CLASS 2" at 315.734,116.17 h1.52
  text "OTHER +/-" at 315.734,112.208 h1.52
  text "BOW & TWIST:" at 289.667,108.22 h1.52
  text "X" at 310.986,108.22 h1.52
  text "ANSI IPC-6012 TYPE 3 CLASS 2" at 315.734,108.22 h1.52
  text "OTHER +/-" at 315.734,104.194 h1.52
  text "DRILLING:" at 287.768,100.676 h1.52
  text "REFERENCE:" at 289.667,97.705 h1.52
  text "X" at 306.132,97.705 h1.52
  text "AS SHOWN" at 310.882,97.705 h1.52
  text "X" at 329.018,97.705 h1.52
  text "NC_DRILL FILES" at 332.498,97.705 h1.52
  text "PTH COPPER THICKNESS:" at 289.667,93.691 h1.52
  text "X" at 318.375,93.691 h1.52
  text "20-30 um" at 321.855,93.691 h1.52
  text "OTHER" at 340.067,93.691 h1.52
  text "BOARD FINISH:" at 287.768,89.653 h1.52
  text "SILKSCREEN:" at 291.711,86.656 h1.52
  text "X" at 315.81,86.656 h1.52
  text "TOP" at 319.01,86.656 h1.52
  text "X" at 328.764,86.656 h1.52
  text "BOTTOM" at 331.99,86.656 h1.52
  text "SILKSCREEN COLOR:" at 291.711,82.414 h1.52
  text "X" at 315.783,82.414 h1.52
  text "WHITE" at 319.01,82.414 h1.52
  text "OTHER" at 331.99,82.414 h1.52
  text "X" at 319.111,78.37 h1.52
  text "GREEN" at 322.338,78.37 h1.52
  text "OTHER" at 338.035,78.37 h1.52
  text "SOLDER RESIST COLOR:" at 291.711,78.096 h1.52
  text "X" at 319.111,74.052 h1.52
  text "MATTE" at 322.338,74.052 h1.52
  text "SEMI-GLOSS" at 338.023,74.036 h1.52
  text "IMMERSION GOLD (ENIG)" at 314.718,69.264 h1.52
  text "ENEPIG" at 348.691,69.18 h1.52
  text "SURFACE FINISH:" at 287.768,69.155 h1.52
  text "X" at 309.969,69.155 h1.52
  text "IMM. TIN/SILVER OR EQUIV" at 296.139,65.167 h1.52
  text "OTHER" at 332.498,65.167 h1.52
  text "ARRAY/PANEL:" at 287.768,60.621 h1.52
  text "CUT AND TRIM PER M1 BOARD OUTLINE" at 314.718,60.512 h1.52
  text "N.C. ROUTE" at 314.718,56.658 h1.52
  text "X" at 331.964,56.658 h1.52
  text "V. SCORE" at 336.714,56.658 h1.52
  text "CERTIFICATION:" at 287.768,53.178 h1.52
  text "MATERIALS AND WORKMANSHIP FOR ALL PCBS" at 306.183,53.178 h1.52
  text "TO MEET OR EXCEED THE REQUIREMENTS OF:" at 306.183,50.689 h1.52
  text "X" at 296.696,47.222 h1.52
  text "ANSI IPC-A-600F CLASS ->" at 300.227,47.222 h1.52
  text "X" at 341.859,47.222 h1.52
  text "2" at 344.88,47.222 h1.52
  text "1" at 336.879,47.184 h1.52
  text "3" at 353.872,47.184 h1.52
  text "X" at 317.373,43.171 h1.52
  text "RoHS" at 320.852,43.171 h1.52
  text "OTHER" at 337.22,43.171 h1.52
  text "PER ORDER" at 347.305,43.171 h1.52
  text "ALL BOARDS MUST MEET OR EXCEED UL94-V0 REQUIREMENTS." at 288.468,38.964 h1.52
  text "PCB MUST BEAR THE UL94V-0 UL REGISTERED MATERIAL ID NUMBER" at 288.468,35.916 h1.52
  text "ADDITIONAL REQUIREMENTS:" at 287.768,31.512 h1.52
  text "MICROSECTION:" at 289.667,28.591 h1.52
  text "YES" at 312.673,28.591 h1.52
  text "REQUIRED" at 334.555,24.625 h1.52
  text "BARE BOARD ELEC. TEST:" at 289.667,24.553 h1.52
  text "NONE" at 322.833,24.553 h1.52
  text "X" at 331.329,24.553 h1.52
  text "PER ORDER" at 349.592,24.553 h1.52
  text ".Layer_Name" at 14.656,-21.806 h1.52
M11 Gerber Information:
  lines w0.254: -7.417,-23.626 160.223,-23.626 ; -7.417,-18.462 160.274,-18.462 ; -7.417,-13.297 -7.417,-28.791 94.31,-28.791 160.274,-28.791 160.274,-13.297 -7.404,-13.297 -7.404,-28.791 32.614,-28.791 ; 55.194,-28.791 55.194,-13.297 ; 87.376,-18.462 87.376,-13.297 ; 108.712,-18.462 108.712,-13.297 ; 124.511,-28.956 124.511,-23.804
  text "ALL ARTWORK VIEWED FROM TOP SIDE" at -5.804,-16.654 h1.52
  text "BOARD #:" at 57.099,-16.654 h1.52
  text ".PRJ_Number" at 70.955,-16.654 h1.52
  text "REV:" at 92.405,-16.654 h1.52
  text ".PCB_Rev" at 99.809,-16.654 h1.52
  text "SVN REV:" at 113.69,-16.654 h1.52
  text ".VersionControl_RevNumber" at 126.543,-16.654 h1.52
  text "LAYER NAME =" at -5.804,-21.806 h1.52
  text "TID #:" at 57.099,-21.819 h1.52
  text ".TID" at 70.955,-21.819 h1.52
  text "PLOT NAME =" at -5.804,-27.034 h1.52
  text ".plot_File_Name" at 14.656,-27.034 h1.52
  text "GENERATED    :" at 57.15,-27.034 h1.52
  text ".Print_Date" at 79.235,-27.034 h1.52
  text ".Print_Time" at 97.752,-27.034 h1.52
  text "TEXAS INSTRUMENTS" at 129.87,-27.034 h1.52
M12 Stackup:
  drawing of 191 lines, arcs and shapes, not listed
  text "Layer" at 248.865,198.882 h1.52
  text "Name" at 259.277,198.882 h1.52
  text "Material" at 282.892,198.882 h1.52
  text "Thickness" at 304.731,198.882 h1.52
  text "Constant" at 321.236,198.882 h1.52
  text "Board Layer Stack" at 335.711,198.882 h1.52
  text "1" at 248.865,195.834 h1.52
  text "Top Overlay" at 259.277,195.834 h1.52
  text "2" at 248.865,192.786 h1.52
  text "Top Solder" at 259.277,192.786 h1.52
  text "Solder Resist" at 282.892,192.786 h1.52
  text "0.40mil" at 304.731,192.786 h1.52
  text "3.5" at 321.236,192.786 h1.52
  text "3" at 248.865,189.738 h1.52
  text "Top Layer" at 259.277,189.738 h1.52
  text "Copper" at 282.892,189.738 h1.52
  text "1.40mil" at 304.731,189.738 h1.52
  text "4" at 248.865,186.69 h1.52
  text "Dielectric1" at 259.277,186.69 h1.52
  text "FR-4" at 282.892,186.69 h1.52
  text "59.20mil" at 304.731,186.69 h1.52
  text "4.8" at 321.236,186.69 h1.52
  text "5" at 248.865,183.642 h1.52
  text "Bottom Layer" at 259.277,183.642 h1.52
  text "Copper" at 282.892,183.642 h1.52
  text "1.40mil" at 304.731,183.642 h1.52
  text "6" at 248.865,180.594 h1.52
  text "Bottom Solder" at 259.277,180.594 h1.52
  text "Solder Resist" at 282.892,180.594 h1.52
  text "0.40mil" at 304.731,180.594 h1.52
  text "3.5" at 321.236,180.594 h1.52
  text "7" at 248.865,177.546 h1.52
  text "Bottom Overlay" at 259.277,177.546 h1.52
  text ".Layer_Name" at 14.656,-21.806 h1.52
M13 Component Bodies Top:
  text ".Layer_Name" at 14.656,-21.806 h1.52
M14 Component Bodies Bottom:
  text ".Layer_Name" at 14.656,-21.806 h1.52
M15 Courtyards Top:
  text ".Layer_Name" at 14.656,-21.806 h1.52
M16 Courtyards Bottom:
  text ".Layer_Name" at 14.656,-21.806 h1.52
Drill Drawing:
  circle w0.254: c37.081,29.528 r0.337
  circle w0.254: c37.081,29.528 r0.562
  lines w0.254: 36.519,21.656 36.8,21.656 37.081,21.375 37.363,21.656 37.644,21.656 37.363,21.937 37.644,22.218 37.363,22.218 37.081,22.499 36.8,22.218 36.519,22.218 36.8,21.937 36.519,21.656 ; 36.519,24.468 37.081,23.905 37.644,24.468 37.081,25.03 36.519,24.468 ; 36.519,26.436 37.644,26.436 37.644,27.56 36.519,27.56 36.519,26.436 ; 36.519,31.496 36.519,31.778 36.8,32.059 36.519,32.34 36.519,32.621 36.8,32.621 37.081,32.34 37.363,32.621 37.644,32.621 37.644,32.34 37.363,32.059 37.644,31.778 37.644,31.496 37.363,31.496 37.081,31.778 36.8,31.496 36.519,31.496 ; 36.519,34.308 36.8,34.308 36.8,34.027 37.363,34.027 37.363,34.308 37.644,34.308 37.644,34.87 37.363,34.87 37.363,35.152 36.8,35.152 36.8,34.87 36.519,34.87 36.519,34.308
  lines w0.305: 35.484,20.616 114.552,20.616 ; 35.484,35.798 114.552,35.798 ; 43.501,18.085 43.501,38.329 ; 51.557,18.085 51.557,38.329 ; 67.35,18.085 67.35,38.329 ; 73.555,18.085 73.555,38.329 ; 82.708,18.085 82.708,38.329 ; 100.73,18.085 100.73,38.329 ; 35.484,18.085 114.552,18.085 114.552,38.329 35.484,38.329 35.484,18.085
  text "Symbol" at 37.002,36.557 h1.83
  text "Quantity" at 44.26,36.557 h1.83
  text "Finished Hole Size" at 52.316,36.557 h1.83
  text "Plated" at 68.109,36.557 h1.83
  text "Hole Type" at 74.315,36.557 h1.83
  text "Drill Layer Pair" at 83.467,36.557 h1.83
  text "Hole Tolerance" at 101.489,36.557 h1.83
  text "3" at 44.26,34.027 h1.52
  text "11.81mil (0.300mm)" at 52.316,34.027 h1.52
  text "PTH" at 68.109,34.027 h1.52
  text "Round" at 74.315,34.027 h1.52
  text "Top Layer - Bottom Layer" at 83.467,34.027 h1.52
  text "49" at 44.26,31.496 h1.52
  text "15.75mil (0.400mm)" at 52.316,31.496 h1.52
  text "PTH" at 68.109,31.496 h1.52
  text "Round" at 74.315,31.496 h1.52
  text "Top Layer - Bottom Layer" at 83.467,31.496 h1.52
  text "2" at 44.26,28.966 h1.52
  text "29.53mil (0.750mm)" at 52.316,28.966 h1.52
  text "PTH" at 68.109,28.966 h1.52
  text "Round" at 74.315,28.966 h1.52
  text "Top Layer - Bottom Layer" at 83.467,28.966 h1.52
  text "14" at 44.26,26.436 h1.52
  text "37.00mil (0.940mm)" at 52.316,26.436 h1.52
  text "PTH" at 68.109,26.436 h1.52
  text "Round" at 74.315,26.436 h1.52
  text "Top Layer - Bottom Layer" at 83.467,26.436 h1.52
  text "+/-2.00mil" at 101.489,26.436 h1.52
  text "2" at 44.26,23.905 h1.52
  text "40.16mil (1.020mm)" at 52.316,23.905 h1.52
  text "PTH" at 68.109,23.905 h1.52
  text "Round" at 74.315,23.905 h1.52
  text "Top Layer - Bottom Layer" at 83.467,23.905 h1.52
  text "1" at 44.26,21.375 h1.52
  text "63.00mil (1.600mm)" at 52.316,21.375 h1.52
  text "PTH" at 68.109,21.375 h1.52
  text "Round" at 74.315,21.375 h1.52
  text "Top Layer - Bottom Layer" at 83.467,21.375 h1.52
  text "71 Total" at 44.26,18.844 h1.52
  text ".Layer_Name" at 14.656,-21.806 h1.52
M17 Embedded Cavity:
  text ".Layer_Name" at 14.656,-21.806 h1.52
M18 Embedded Assembly:
  text ".Layer_Name" at 14.656,-21.806 h1.52
M19 Embedded Keepout:
  text ".Layer_Name" at 14.656,-21.806 h1.52

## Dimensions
0,-10.16 to 25.4,-10.16 on M2 Board Dimensions
0,0 to 0,38.1 on M2 Board Dimensions
0,0 to 25.4,0 on M2 Board Dimensions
